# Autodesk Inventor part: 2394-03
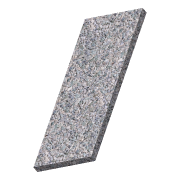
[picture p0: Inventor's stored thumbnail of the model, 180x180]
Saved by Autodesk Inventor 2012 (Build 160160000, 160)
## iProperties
Created: 2011-02
Part Number: 2394-03
Material: Default
Document SubType Name: Modeling
Designer: Beta-8540w
Density: 1 g/cm^3
bottom_thickness: 0.130 in
Author: Beta-8540w
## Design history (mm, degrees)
derived "c15-11.ipt" dims "d2" = 15.875, "d3" = 0, "d4" = 4.4958, "d12" = 4.4958, "d22" = 6.35, "d23" = 0, "d24" = 9.652, "d26" = 6.35, "d27" = 0, "d72" = 19.05, "d73" = 19.05, "d74" = 3.302, "d75" = 3.302, "d76" = 12.7, "drawer_width" = 406.4, "drawer_height" = 152.4, "dbl_pull_width" = 76.2, "back_width" = 342.9, "bottom_thickness" = 3.302
body "Solid1"
feature "Solid1::c15-11.ipt" dims "d2" = 15.875, "d3" = 0, "d4" = 4.4958, "d12" = 4.4958, "d22" = 6.35, "d23" = 0, "d24" = 9.652, "d26" = 6.35, "d27" = 0, "d72" = 19.05, "d73" = 19.05, "d74" = 3.302, "d75" = 3.302, "d76" = 12.7, "drawer_width" = 406.4, "drawer_height" = 152.4, "dbl_pull_width" = 76.2, "back_width" = 342.9, "bottom_thickness" = 3.302, "ScaleForDerivedMember" = 10
tag "TaggingFeature1"
